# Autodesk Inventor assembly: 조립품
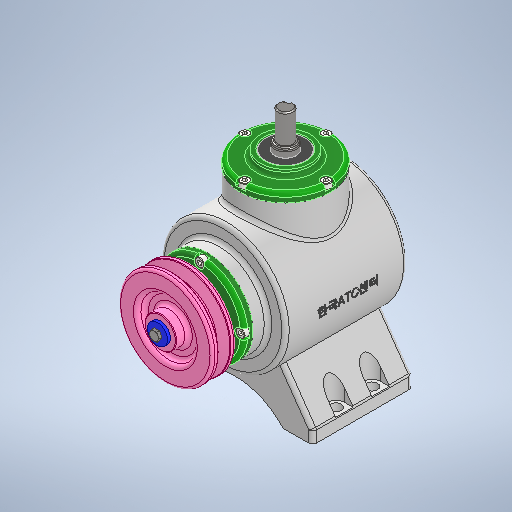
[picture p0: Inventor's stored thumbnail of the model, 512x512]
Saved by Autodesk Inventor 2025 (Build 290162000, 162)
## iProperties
Created: 2024-07
Part Number: 조립품
Document SubType Name: Assembly
Designer: 학생
Author: 학생
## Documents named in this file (15)
- C:\Users\학생\Desktop\740709V1005\조립품.iam
- C:\Users\학생\Desktop\740709V1005\본체.ipt
- C:\Users\학생\Desktop\740709V1005\Ű 4 x 4 x 14\Ű 4 x 4 x 14.ipt
- C:\Users\학생\Desktop\740709V1005\Ű 5 x 5 x 14\Ű 5 x 5 x 14.ipt
- C:\Users\학생\Desktop\740709V1005\V-벨트풀리\V-벨트풀리.ipt
- C:\Users\학생\Desktop\740709V1005\메인 베벨기어\메인 베벨기어.ipt
- C:\Users\학생\Desktop\740709V1005\메인 축\메인 축.ipt
- C:\Users\학생\Desktop\740709V1005\베어링 6203\베어링 6203.ipt
- C:\Users\학생\Desktop\740709V1005\볼트 M4 x 10\볼트 M4 x 10.ipt
- C:\Users\학생\Desktop\740709V1005\서브 베벨기어\서브 베벨기어.ipt
- C:\Users\학생\Desktop\740709V1005\서브 축\서브 축.ipt
- C:\Users\학생\Desktop\740709V1005\오일실 17 x 32 x 8\오일실 17 x 32 x 8.ipt
- C:\Users\학생\Desktop\740709V1005\와셔 4 x 16\와셔 4 x 16.ipt
- C:\Users\학생\Desktop\740709V1005\육각볼트 M4 x 8\육각볼트 M4 x 8.ipt
- C:\Users\학생\Desktop\740709V1005\커버\커버.ipt
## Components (4 placed, 3 different names)
1. V-벨트풀리:1 — 각도:3
2. Ű 4 x 4 x 14:2 — 각도:3
3. Ű 5 x 5 x 14:4 — 각도:2
4. Ű 4 x 4 x 14:3 — 각도:4
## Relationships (3: Angle 3)
- 각도:2 [Angle]: Ű 5 x 5 x 14:4
- 각도:3 [Angle]: V-벨트풀리:1 ↔ Ű 4 x 4 x 14:2
- 각도:4 [Angle]: Ű 4 x 4 x 14:3
